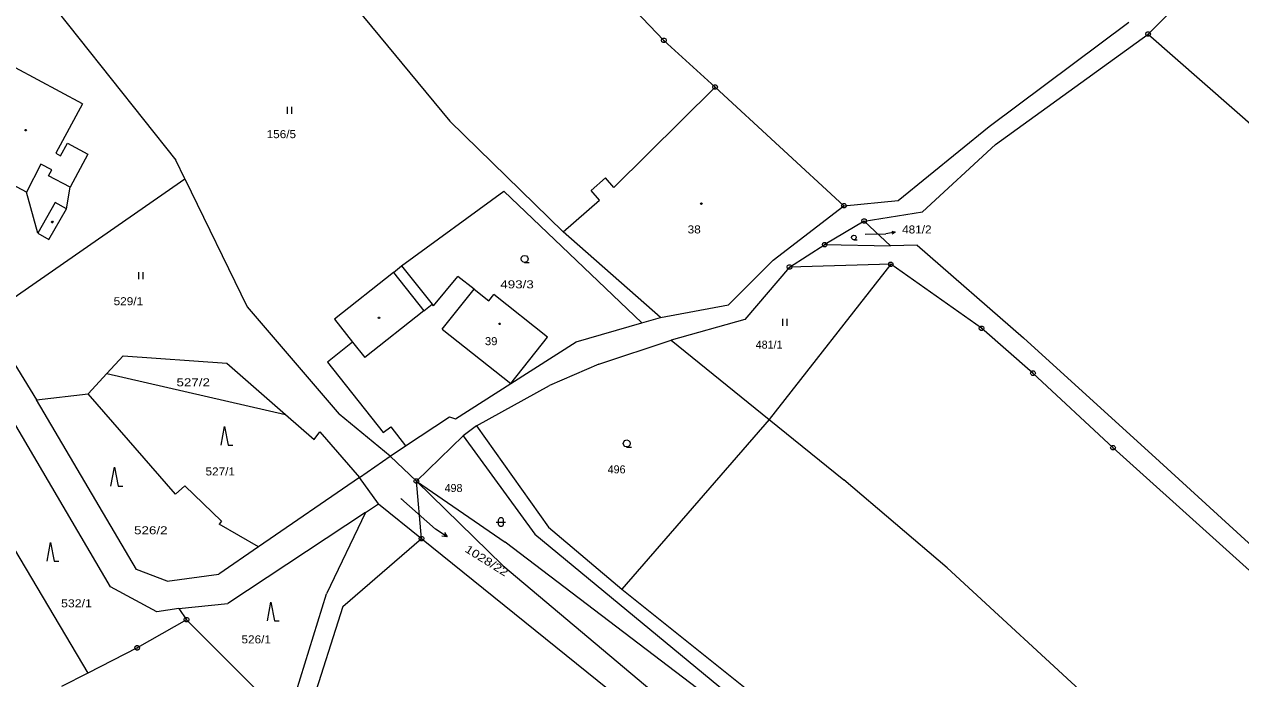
# Model space of a CAD drawing. Extents: x -687390 to -684106, y -954833 to -951648.
# Drawn here: x -686934.3 to -686675.9, y -952885.7 to -952746.6 of the extents above; entities that cross this region are included whole.
import ezdxf

# ---------------------------------------------------------------- set-up
doc = ezdxf.new("R2010")
doc.units = 0
doc.header["$LTSCALE"] = 0.68
doc.header["$PDMODE"] = 32
doc.header["$PDSIZE"] = 0.34
for name, color, linetype, lineweight in [('1', 7, 'Continuous', 13), ('3', 7, 'Continuous', 13), ('4', 7, 'Continuous', 13), ('5', 7, 'Continuous', 13), ('7', 7, 'Continuous', 13), ('8', 7, 'Continuous', 13)]:
    doc.layers.add(name, color=color, linetype=linetype, lineweight=lineweight)
doc.layers.add('2', color=7, linetype='Continuous')

msp = doc.modelspace()

# ---------------------------------------------------------------- linework, layer by layer
at = {"layer": '1'}
for p, q in [((-686695.55, -952748.71), (-686660.3, -952713.48)), ((-686874.74, -952729.93), (-686843.87, -952767.2)), ((-686929.71, -952740.7), (-686902.11, -952775.53)), ((-686921.94, -952763.55), (-686936.14, -952755.87)), ((-686787.53, -952759.97), (-686809.02, -952781.33)), ((-686921.94, -952763.55), (-686927.61, -952774.05)), ((-686819.82, -952790.71), (-686843.87, -952767.2)), ((-686927.61, -952774.05), (-686926.56, -952774.6)), ((-686933.85, -952782.3), (-686944.59, -952776.68)), ((-686900.19, -952779.49), (-686886.94, -952806.65)), ((-686813.88, -952781.93), (-686810.81, -952779.27)), ((-686809.02, -952781.33), (-686810.81, -952779.27)), ((-686931.43, -952791), (-686933.85, -952782.3)), ((-686925.34, -952785.87), (-686924.52, -952781.24)), ((-686854.12, -952797.97), (-686832.39, -952782.12)), ((-686803.08, -952810.05), (-686832.39, -952782.12)), ((-686929.08, -952792.37), (-686925.34, -952785.87)), ((-686755.86, -952788.44), (-686764.24, -952793.45)), ((-686931.43, -952791), (-686929.08, -952792.37)), ((-686799.14, -952808.92), (-686819.82, -952790.71)), ((-686744.64, -952793.54), (-686750.29, -952793.68)), ((-686744.64, -952793.54), (-686721.99, -952813.23)), ((-686855.88, -952799.35), (-686854.12, -952797.97)), ((-686854.12, -952797.97), (-686847.67, -952806.12)), ((-686750.22, -952797.63), (-686776.04, -952830.63)), ((-686855.88, -952799.35), (-686868.41, -952809.3)), ((-686847.38, -952806.48), (-686842.16, -952800.22)), ((-686838.73, -952802.93), (-686842.16, -952800.22)), ((-686838.73, -952802.93), (-686835.61, -952805.4)), ((-686835.61, -952805.4), (-686834.56, -952804.06)), ((-686886.94, -952806.65), (-686867.38, -952829.45)), ((-686847.38, -952806.48), (-686847.67, -952806.12)), ((-686812.2, -952818.86), (-686796.86, -952813.77)), ((-686796.86, -952813.77), (-686776.04, -952830.63)), ((-686693.09, -952839.54), (-686721.99, -952813.23)), ((-686913.31, -952817.06), (-686891.29, -952818.65)), ((-686869.89, -952818.39), (-686858.02, -952833.34)), ((-686812.2, -952818.86), (-686822.72, -952823.4)), ((-686916.76, -952820.84), (-686878.79, -952829.53)), ((-686838.22, -952831.93), (-686822.72, -952823.4)), ((-686902.17, -952846.46), (-686920.73, -952825.17)), ((-686953.43, -952829.54), (-686920.81, -952884.49)), ((-686843.98, -952830.01), (-686842.68, -952830.48)), ((-686858.02, -952833.34), (-686856.43, -952832.14)), ((-686856.43, -952832.14), (-686853.33, -952836.22)), ((-686838.22, -952831.93), (-686841.02, -952834.1)), ((-686776.04, -952830.63), (-686807.34, -952866.66)), ((-686776.04, -952830.63), (-686760.17, -952843.42)), ((-686851, -952843.7), (-686841.02, -952834.1)), ((-686856.57, -952838.36), (-686851, -952843.7)), ((-686693.09, -952839.54), (-686653.72, -952875.6)), ((-686902.17, -952846.46), (-686900.17, -952844.72)), ((-686900.17, -952844.72), (-686892.36, -952852.23)), ((-686851, -952843.7), (-686832.15, -952856.7)), ((-686849.89, -952855.92), (-686851, -952843.7)), ((-686738.23, -952862.13), (-686760.17, -952843.42)), ((-686861.77, -952850.35), (-686891.05, -952869.7)), ((-686861.77, -952850.35), (-686870.09, -952867.67)), ((-686892.36, -952852.23), (-686892.92, -952852.81)), ((-686884.55, -952857.65), (-686892.92, -952852.81)), ((-686866.64, -952870.3), (-686849.89, -952855.92)), ((-686781.53, -952895.13), (-686832.15, -952856.7)), ((-686903.93, -952864.94), (-686892.98, -952863.44)), ((-686672.7, -952922.52), (-686738.23, -952862.13)), ((-686878.46, -952894.57), (-686870.09, -952867.67)), ((-686901.42, -952870.78), (-686891.05, -952869.7)), ((-686866.64, -952870.3), (-686874.83, -952896.01))]:
    msp.add_line(p, q, dxfattribs=at)
for points in [[(-686760.15, -952785.19), (-686787.53, -952759.97), (-686798.41, -952750.05), (-686829.06, -952717.91), (-686843.83, -952697.72), (-686857.28, -952682.32), (-686867.65, -952672.29), (-686876.47, -952664.65), (-686896.54, -952649.2), (-686899.78, -952646.91), (-686884.22, -952620.8)], [(-686760.15, -952785.19), (-686748.64, -952784.07), (-686729.34, -952768.34), (-686699.65, -952746.17)], [(-686755.86, -952788.44), (-686743.45, -952786.47), (-686727.96, -952772.17), (-686695.55, -952748.71)], [(-686695.55, -952748.71), (-686654.22, -952784.95), (-686599.33, -952833.8), (-686574.97, -952856.02)], [(-686926.56, -952774.6), (-686925.14, -952771.9), (-686920.79, -952774.21), (-686924.52, -952781.24)], [(-686942.54, -952808.88), (-686900.19, -952779.49), (-686902.11, -952775.53)], [(-686819.82, -952790.71), (-686812.09, -952783.98), (-686813.88, -952781.93)], [(-686799.14, -952808.92), (-686784.7, -952806.26), (-686775.22, -952796.78), (-686760.15, -952785.19)], [(-686551.59, -953009.58), (-686581.57, -952958.44), (-686596.23, -952936.18), (-686638.74, -952894.41), (-686702.99, -952836.61), (-686720, -952820.76), (-686730.92, -952811.22), (-686750.22, -952797.63), (-686771.71, -952798.21), (-686764.24, -952793.45), (-686750.29, -952793.68), (-686755.86, -952788.44)], [(-686771.71, -952798.21), (-686781.2, -952809.39), (-686796.86, -952813.77)], [(-686830.94, -952822.96), (-686823.13, -952813.11), (-686834.56, -952804.06)], [(-686942.54, -952808.88), (-686931.71, -952826.41), (-686920.73, -952825.17)], [(-686868.41, -952809.3), (-686864.56, -952814.16), (-686869.89, -952818.39)], [(-686817.08, -952814.09), (-686803.08, -952810.05), (-686799.14, -952808.92)], [(-686842.68, -952830.48), (-686830.94, -952822.96), (-686817.08, -952814.09)], [(-686920.73, -952825.17), (-686916.76, -952820.84), (-686913.31, -952817.06)], [(-686891.29, -952818.65), (-686878.79, -952829.53), (-686872.7, -952834.83)], [(-686901.42, -952870.78), (-686906.16, -952871.49), (-686915.95, -952866.19), (-686941.67, -952822.48)], [(-686903.93, -952864.94), (-686910.45, -952862.5), (-686931.71, -952826.41)], [(-686872.7, -952834.83), (-686871.51, -952833.19), (-686863.11, -952842.95), (-686856.57, -952838.36), (-686867.38, -952829.45)], [(-686856.57, -952838.36), (-686853.33, -952836.22), (-686843.98, -952830.01)], [(-686838.22, -952831.93), (-686822.92, -952853.47), (-686807.34, -952866.66), (-686776.21, -952891.55)], [(-686841.02, -952834.1), (-686825.81, -952854.97), (-686778.58, -952894)], [(-686863.11, -952842.95), (-686884.55, -952857.65), (-686892.98, -952863.44)], [(-686861.77, -952850.35), (-686859.05, -952848.49), (-686863.11, -952842.95)], [(-686851, -952843.7), (-686832.64, -952861.61), (-686782.67, -952903.64), (-686781.1, -952910.23)], [(-686859.05, -952848.49), (-686849.89, -952855.92), (-686788.47, -952905.46)], [(-686901.42, -952870.78), (-686899.83, -952873.14), (-686910.31, -952879.12)], [(-686899.83, -952873.14), (-686878.46, -952894.57), (-686883.9, -952906.93)], [(-686910.31, -952879.12), (-686920.81, -952884.49), (-686926.37, -952887.33)]]:
    msp.add_lwpolyline(points, dxfattribs=at)
at = {"layer": '3'}
for p, q in [((-686878.43, -952764.15), (-686878.43, -952765.65)), ((-686877.43, -952765.65), (-686877.43, -952764.15)), ((-686910.05, -952799.29), (-686910.05, -952800.79)), ((-686909.05, -952800.79), (-686909.05, -952799.29)), ((-686773.2, -952809.2), (-686773.2, -952810.7)), ((-686772.2, -952810.7), (-686772.2, -952809.2))]:
    msp.add_line(p, q, dxfattribs=at)
for points in [[(-686758.03, -952792.41), (-686758.285, -952792.343), (-686758.466, -952792.162), (-686758.532, -952791.914), (-686758.466, -952791.666), (-686758.285, -952791.485), (-686758.037, -952791.418), (-686757.789, -952791.485), (-686757.608, -952791.666), (-686757.541, -952791.921), (-686757.608, -952792.176), (-686757.789, -952792.356), (-686758.043, -952792.423), (-686757.373, -952792.423)], [(-686827.99, -952797.22), (-686828.37, -952797.12), (-686828.64, -952796.85), (-686828.74, -952796.48), (-686828.64, -952796.11), (-686828.37, -952795.84), (-686828, -952795.74), (-686827.63, -952795.84), (-686827.36, -952796.11), (-686827.26, -952796.49), (-686827.36, -952796.87), (-686827.63, -952797.14), (-686828.01, -952797.24), (-686827.01, -952797.24)], [(-686892.48, -952836.08), (-686891.73, -952832.08), (-686890.98, -952836.08), (-686889.98, -952836.08)], [(-686806.3, -952836.43), (-686806.68, -952836.33), (-686806.95, -952836.06), (-686807.05, -952835.69), (-686806.95, -952835.32), (-686806.68, -952835.05), (-686806.31, -952834.95), (-686805.94, -952835.05), (-686805.67, -952835.32), (-686805.57, -952835.7), (-686805.67, -952836.08), (-686805.94, -952836.35), (-686806.32, -952836.45), (-686805.32, -952836.45)], [(-686915.87, -952844.75), (-686915.12, -952840.75), (-686914.37, -952844.75), (-686913.37, -952844.75)], [(-686834.03, -952852.4), (-686832.76, -952852.4), (-686832.03, -952852.4)], [(-686929.44, -952860.73), (-686928.69, -952856.73), (-686927.94, -952860.73), (-686926.94, -952860.73)], [(-686882.63, -952873.39), (-686881.88, -952869.39), (-686881.13, -952873.39), (-686880.13, -952873.39)]]:
    msp.add_lwpolyline(points, dxfattribs=at)
msp.add_lwpolyline([(-686833.53, -952851.9), (-686833.43, -952851.61), (-686833.18, -952851.43), (-686832.87, -952851.43), (-686832.62, -952851.61), (-686832.52, -952851.9), (-686832.52, -952852.9), (-686832.62, -952853.19), (-686832.87, -952853.37), (-686833.18, -952853.37), (-686833.43, -952853.19), (-686833.53, -952852.9)], close=True, dxfattribs=at)
msp.add_point((-686790.44, -952784.73), dxfattribs=at)
at = {"layer": '4'}
for p, q in [((-686855.88, -952799.35), (-686849.41, -952807.51)), ((-686845.48, -952811.44), (-686838.73, -952802.93)), ((-686849.41, -952807.51), (-686847.67, -952806.12)), ((-686849.41, -952807.51), (-686861.96, -952817.45)), ((-686845.48, -952811.44), (-686830.94, -952822.96)), ((-686864.56, -952814.16), (-686861.96, -952817.45))]:
    msp.add_line(p, q, dxfattribs=at)
for points in [[(-686924.52, -952781.24), (-686929.11, -952778.81), (-686928.46, -952777.56), (-686930.74, -952776.35), (-686933.85, -952782.3)], [(-686925.34, -952785.87), (-686927.7, -952784.51), (-686931.43, -952791)]]:
    msp.add_lwpolyline(points, dxfattribs=at)
at = {"layer": '5'}
for points in [[(-686933.9, -952768.97), (-686933.81, -952769.12), (-686933.9, -952769.27), (-686934.08, -952769.27), (-686934.17, -952769.12), (-686934.08, -952768.97)], [(-686928.27, -952788.5), (-686928.18, -952788.65), (-686928.27, -952788.8), (-686928.45, -952788.8), (-686928.54, -952788.65), (-686928.45, -952788.5)], [(-686858.85, -952808.86), (-686858.76, -952809.01), (-686858.85, -952809.16), (-686859.03, -952809.16), (-686859.12, -952809.01), (-686859.03, -952808.86)], [(-686833.23, -952810.12), (-686833.14, -952810.27), (-686833.23, -952810.42), (-686833.41, -952810.42), (-686833.5, -952810.27), (-686833.41, -952810.12)]]:
    msp.add_lwpolyline(points, close=True, dxfattribs=at)
at = {"layer": '7'}
for p, q in [((-686755.64, -952791.21), (-686751.28, -952791.14)), ((-686749.296, -952790.821), (-686751.28, -952791.14)), ((-686854.31, -952847.42), (-686846.96, -952853.9)), ((-686844.451, -952855.545), (-686846.96, -952853.9))]:
    msp.add_line(p, q, dxfattribs=at)
for points in [[(-686750.01, -952790.596), (-686749.296, -952790.821), (-686749.904, -952791.258)], [(-686845.013, -952854.579), (-686844.451, -952855.545), (-686845.562, -952855.415)]]:
    msp.add_lwpolyline(points, dxfattribs=at)
at = {"layer": '8'}
for p, q in [((-686798.53, -952750.05), (-686798.29, -952750.05)), ((-686695.67, -952748.71), (-686695.43, -952748.71)), ((-686787.65, -952759.97), (-686787.41, -952759.97)), ((-686760.27, -952785.19), (-686760.03, -952785.19)), ((-686755.98, -952788.44), (-686755.74, -952788.44)), ((-686764.36, -952793.45), (-686764.12, -952793.45)), ((-686771.83, -952798.21), (-686771.59, -952798.21)), ((-686750.34, -952797.63), (-686750.1, -952797.63)), ((-686731.04, -952811.22), (-686730.8, -952811.22)), ((-686720.12, -952820.76), (-686719.88, -952820.76)), ((-686703.11, -952836.61), (-686702.87, -952836.61)), ((-686851.12, -952843.7), (-686850.88, -952843.7)), ((-686850.01, -952855.92), (-686849.77, -952855.92)), ((-686899.95, -952873.14), (-686899.71, -952873.14)), ((-686910.43, -952879.12), (-686910.19, -952879.12))]:
    msp.add_line(p, q, dxfattribs=at)
for points in [[(-686798.26, -952749.57), (-686798.01, -952749.75), (-686797.91, -952750.04), (-686798.01, -952750.33), (-686798.26, -952750.51), (-686798.57, -952750.51), (-686798.82, -952750.33), (-686798.92, -952750.04), (-686798.82, -952749.75), (-686798.57, -952749.57)], [(-686695.4, -952748.23), (-686695.15, -952748.41), (-686695.05, -952748.7), (-686695.15, -952748.99), (-686695.4, -952749.17), (-686695.71, -952749.17), (-686695.96, -952748.99), (-686696.06, -952748.7), (-686695.96, -952748.41), (-686695.71, -952748.23)], [(-686787.38, -952759.49), (-686787.13, -952759.67), (-686787.03, -952759.96), (-686787.13, -952760.25), (-686787.38, -952760.43), (-686787.69, -952760.43), (-686787.94, -952760.25), (-686788.04, -952759.96), (-686787.94, -952759.67), (-686787.69, -952759.49)], [(-686760, -952784.71), (-686759.75, -952784.89), (-686759.65, -952785.18), (-686759.75, -952785.47), (-686760, -952785.65), (-686760.31, -952785.65), (-686760.56, -952785.47), (-686760.66, -952785.18), (-686760.56, -952784.89), (-686760.31, -952784.71)], [(-686755.71, -952787.96), (-686755.46, -952788.14), (-686755.36, -952788.43), (-686755.46, -952788.72), (-686755.71, -952788.9), (-686756.02, -952788.9), (-686756.27, -952788.72), (-686756.37, -952788.43), (-686756.27, -952788.14), (-686756.02, -952787.96)], [(-686764.09, -952792.97), (-686763.84, -952793.15), (-686763.74, -952793.44), (-686763.84, -952793.73), (-686764.09, -952793.91), (-686764.4, -952793.91), (-686764.65, -952793.73), (-686764.75, -952793.44), (-686764.65, -952793.15), (-686764.4, -952792.97)], [(-686771.56, -952797.73), (-686771.31, -952797.91), (-686771.21, -952798.2), (-686771.31, -952798.49), (-686771.56, -952798.67), (-686771.87, -952798.67), (-686772.12, -952798.49), (-686772.22, -952798.2), (-686772.12, -952797.91), (-686771.87, -952797.73)], [(-686750.07, -952797.15), (-686749.82, -952797.33), (-686749.72, -952797.62), (-686749.82, -952797.91), (-686750.07, -952798.09), (-686750.38, -952798.09), (-686750.63, -952797.91), (-686750.73, -952797.62), (-686750.63, -952797.33), (-686750.38, -952797.15)], [(-686730.77, -952810.74), (-686730.52, -952810.92), (-686730.42, -952811.21), (-686730.52, -952811.5), (-686730.77, -952811.68), (-686731.08, -952811.68), (-686731.33, -952811.5), (-686731.43, -952811.21), (-686731.33, -952810.92), (-686731.08, -952810.74)], [(-686719.85, -952820.28), (-686719.6, -952820.46), (-686719.5, -952820.75), (-686719.6, -952821.04), (-686719.85, -952821.22), (-686720.16, -952821.22), (-686720.41, -952821.04), (-686720.51, -952820.75), (-686720.41, -952820.46), (-686720.16, -952820.28)], [(-686702.84, -952836.13), (-686702.59, -952836.31), (-686702.49, -952836.6), (-686702.59, -952836.89), (-686702.84, -952837.07), (-686703.15, -952837.07), (-686703.4, -952836.89), (-686703.5, -952836.6), (-686703.4, -952836.31), (-686703.15, -952836.13)], [(-686850.85, -952843.22), (-686850.6, -952843.4), (-686850.5, -952843.69), (-686850.6, -952843.98), (-686850.85, -952844.16), (-686851.16, -952844.16), (-686851.41, -952843.98), (-686851.51, -952843.69), (-686851.41, -952843.4), (-686851.16, -952843.22)], [(-686849.74, -952855.44), (-686849.49, -952855.62), (-686849.39, -952855.91), (-686849.49, -952856.2), (-686849.74, -952856.38), (-686850.05, -952856.38), (-686850.3, -952856.2), (-686850.4, -952855.91), (-686850.3, -952855.62), (-686850.05, -952855.44)], [(-686899.68, -952872.66), (-686899.43, -952872.84), (-686899.33, -952873.13), (-686899.43, -952873.42), (-686899.68, -952873.6), (-686899.99, -952873.6), (-686900.24, -952873.42), (-686900.34, -952873.13), (-686900.24, -952872.84), (-686899.99, -952872.66)], [(-686910.16, -952878.64), (-686909.91, -952878.82), (-686909.81, -952879.11), (-686909.91, -952879.4), (-686910.16, -952879.58), (-686910.47, -952879.58), (-686910.72, -952879.4), (-686910.82, -952879.11), (-686910.72, -952878.82), (-686910.47, -952878.64)]]:
    msp.add_lwpolyline(points, close=True, dxfattribs=at)

# ---------------------------------------------------------------- texts
at = {"layer": '2'}
for s, height, width, p in [('156/5', 1.7, 1.1, (-686882.805, -952770.83)), ('38', 1.7, 1.1, (-686793.365, -952791.07)), ('481/2', 0.1, 1.1, (-686755.612, -952791.21)), ('493/3', 1.7, 1.25, (-686833.165, -952802.74)), ('529/1', 1.7, 1.1, (-686915.305, -952806.32)), ('39', 1.7, 1.05, (-686836.425, -952814.81)), ('527/2', 1.7, 1.25, (-686901.955, -952823.55)), ('527/1', 1.7, 1.1, (-686895.785, -952842.49)), ('1028/22', 0.1, 1.15, (-686854.264, -952847.42)), ('526/2', 1.7, 1.25, (-686910.965, -952854.99)), ('532/1', 1.7, 1.15, (-686926.475, -952870.51)), ('526/1', 1.7, 1.1, (-686888.145, -952878.17))]:
    msp.add_text(s, height=height, dxfattribs=dict(at, width=width)).set_placement(p)
for s, p in [('481/1', (-686778.905, -952815.55)), ('496', (-686810.355, -952842.05)), ('498', (-686844.995, -952846.01))]:
    msp.add_text(s, height=1.7, dxfattribs=at).set_placement(p)
at = {"layer": '7', "width": 1.1}
msp.add_text('481/2', height=1.7, dxfattribs=at).set_placement((-686747.805, -952791.08))
at = {"layer": '7', "width": 1.25}
msp.add_text('1028/22', height=1.7, rotation=327.961, dxfattribs=at).set_placement((-686840.846, -952858.588))

doc.saveas('drawing.dxf')
